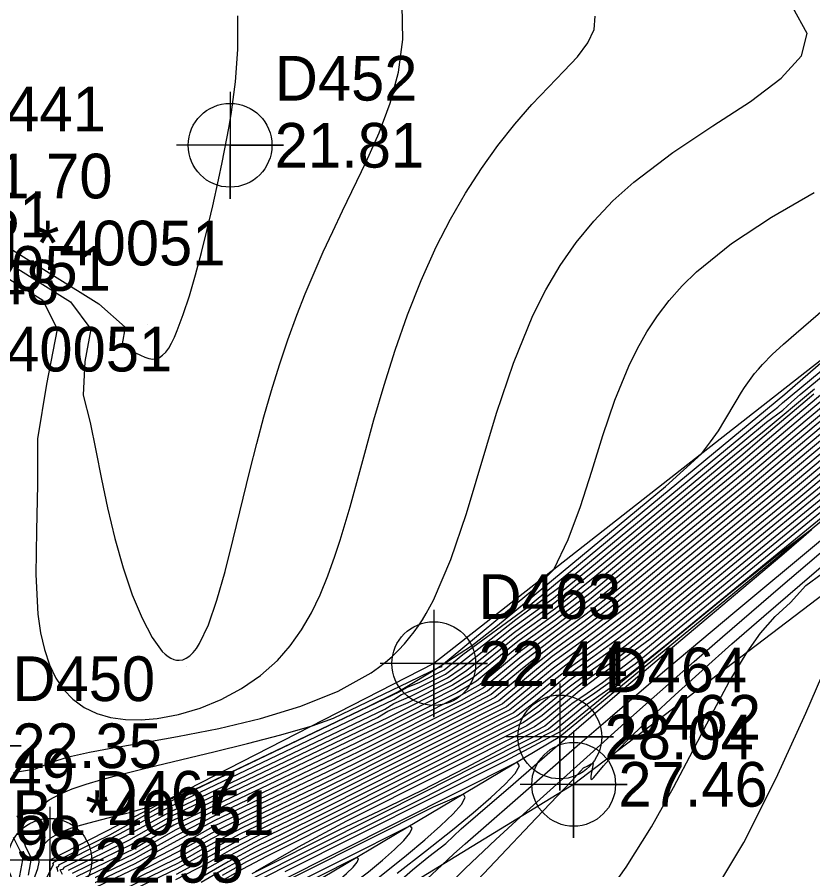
# Model space of a CAD drawing. Extents: x 2356077 to 2359823, y 225951 to 227822.
# Drawn here: x 2356632.82 to 2356677.38, y 226991.05 to 227038.77 of the extents above; entities that cross this region are included whole.
import ezdxf

# ---------------------------------------------------------------- set-up
doc = ezdxf.new("R2010")
doc.units = 0
for name, color, linetype in [('DTM Contours Major', 7, 'Continuous'), ('DTM Contours Minor', 7, 'Continuous'), ('Exist DTM Breakline', 7, 'Continuous'), ('Exist DTM Breakline Cogo Comment', 7, 'Continuous'), ('Exist DTM Breakline Cogo Elevation', 7, 'Continuous'), ('Exist DTM Breakline Cogo Number', 7, 'Continuous'), ('Exist DTM Breakline Cogo Point CELL', 7, 'Continuous'), ('Exist DTM Regular Point CELL', 7, 'Continuous'), ('Exist DTM Regular Point Cogo Elevation', 7, 'Continuous'), ('Exist DTM Regular Point Cogo Number', 7, 'Continuous'), ('PH Exist DTM Point', 7, 'Continuous')]:
    doc.layers.add(name, color=color, linetype=linetype)

msp = doc.modelspace()

# ---------------------------------------------------------------- linework, layer by layer
at = {"layer": 'DTM Contours Major'}
for points in [[(2356629.303, 227026.9), (2356635.813, 227022.844), (2356636.959, 227021.315), (2356636.611, 227019.492), (2356636.518, 227017.607), (2356636.907, 227016.089), (2356637.236, 227014.518), (2356637.546, 227012.918), (2356637.877, 227011.307), (2356638.289, 227009.599), (2356638.759, 227007.961), (2356639.273, 227006.452), (2356639.818, 227005.13), (2356640.383, 227004.052), (2356640.953, 227003.277), (2356641.114, 227003.12), (2356641.274, 227002.992), (2356641.434, 227002.894), (2356641.592, 227002.825), (2356641.749, 227002.787), (2356641.905, 227002.779), (2356642.102, 227002.813), (2356642.297, 227002.897), (2356642.488, 227003.029), (2356642.675, 227003.21), (2356642.859, 227003.439), (2356643.039, 227003.714), (2356643.54, 227004.766), (2356644.015, 227006.137), (2356644.474, 227007.756), (2356644.926, 227009.551), (2356645.849, 227013.384), (2356646.238, 227014.909), (2356646.644, 227016.408), (2356647.07, 227017.877), (2356647.517, 227019.316), (2356647.988, 227020.72), (2356648.485, 227022.088), (2356648.957, 227023.29), (2356649.45, 227024.468), (2356649.963, 227025.629), (2356650.493, 227026.781), (2356651.039, 227027.931), (2356652.365, 227030.668), (2356653.092, 227032.288), (2356653.718, 227033.96), (2356654.182, 227035.698), (2356654.422, 227037.517), (2356654.378, 227039.432)], [(2356633.859, 226989.395), (2356634.839, 226991.313), (2356634.871, 226991.324), (2356634.819, 226991.422), (2356634.869, 226991.412), (2356634.853, 226991.452), (2356634.861, 226991.473), (2356634.875, 226991.491), (2356638.015, 226993.019), (2356641.035, 226994.707), (2356654.257, 227001.028), (2356654.671, 227001.273), (2356655.363, 227001.561), (2356656.724, 227002.245), (2356657.776, 227003.109), (2356661.351, 227005.722), (2356675.811, 227017.665), (2356679.39, 227020.795)], [(2356680.26, 227019.691), (2356676.405, 227016.442), (2356673.246, 227013.767), (2356671.44, 227012.284), (2356665.065, 227007.018), (2356662.952, 227005.358), (2356660.848, 227003.837), (2356658.345, 227001.807), (2356657.32, 227001.179), (2356653.298, 226999.159), (2356652.183, 226998.621), (2356641.605, 226993.564), (2356639.419, 226992.247), (2356636.123, 226990.671)], [(2356681.648, 227017.188), (2356676.515, 227012.882), (2356674.805, 227011.467), (2356668.104, 227005.979), (2356666.778, 227004.932), (2356665.422, 227003.904), (2356664.055, 227002.904), (2356662.792, 227001.935), (2356661.625, 227000.971), (2356660.417, 227000.005), (2356650.424, 226994.985), (2356648.485, 226994.02), (2356646.654, 226993.145), (2356644.955, 226992.264), (2356643.381, 226991.381), (2356641.685, 226990.498)], [(2356677.954, 227015.918), (2356673.699, 227012.35), (2356669.7, 227009.074), (2356667.996, 227007.667), (2356666.281, 227006.272), (2356664.577, 227004.956), (2356662.849, 227003.677), (2356661.117, 227002.324), (2356659.36, 227000.872), (2356657.9, 227000.106), (2356651.822, 226997.052), (2356650.253, 226996.282), (2356645.811, 226994.158), (2356643.724, 226993.117), (2356641.848, 226992.056), (2356639.505, 226990.872)], [(2356678.591, 227012.78), (2356668.345, 227004.388), (2356666.512, 227002.96), (2356665.495, 227002.224), (2356664.478, 227001.511), (2356663.553, 227000.791), (2356662.211, 226999.683), (2356661.352, 226999.11), (2356646.791, 226991.794), (2356645.437, 226991.091), (2356644.152, 226990.361)], [(2356654.064, 226990.278), (2356654.969, 226991.051), (2356655.877, 226991.804), (2356656.824, 226992.535), (2356657.685, 226993.344), (2356658.618, 226994.144), (2356660.59, 226995.854), (2356662.791, 226997.768), (2356664.937, 226999.619), (2356666.938, 227001.329), (2356669.279, 227003.313), (2356675.635, 227008.669), (2356676.856, 227009.707), (2356677.291, 227010.099), (2356676.773, 227009.713), (2356675.381, 227008.638), (2356672.559, 227006.394), (2356663.328, 226998.833), (2356660.139, 226997.135), (2356647.814, 226990.943)], [(2356671.491, 226989.227), (2356673.506, 226992.595), (2356675.328, 226996.194), (2356676.977, 226999.821), (2356678.47, 227003.273)]]:
    msp.add_lwpolyline(points, dxfattribs=at)
at = {"layer": 'DTM Contours Minor'}
for points in [[(2356629.646, 227027.562), (2356637.397, 227022.732), (2356638.874, 227021.42), (2356638.698, 227020.497), (2356638.948, 227020.299), (2356639.208, 227020.135), (2356639.449, 227019.991), (2356639.724, 227019.845), (2356639.974, 227019.735), (2356640.203, 227019.666), (2356640.414, 227019.639), (2356640.61, 227019.657), (2356640.792, 227019.723), (2356640.973, 227019.846), (2356641.145, 227020.024), (2356641.311, 227020.254), (2356641.473, 227020.534), (2356641.633, 227020.862), (2356641.794, 227021.237), (2356642.128, 227022.134), (2356642.469, 227023.182), (2356642.81, 227024.347), (2356643.147, 227025.596), (2356643.474, 227026.894), (2356643.785, 227028.208), (2356644.108, 227029.656), (2356644.311, 227030.625), (2356644.556, 227031.876), (2356644.696, 227032.656), (2356644.827, 227033.459), (2356645.045, 227035.152), (2356645.177, 227036.953), (2356645.187, 227038.846)], [(2356632.631, 226996.502), (2356633.853, 226996.699), (2356634.691, 226997.071), (2356635.703, 226997.379), (2356636.873, 226997.645), (2356638.184, 226997.889), (2356639.617, 226998.134), (2356641.808, 226998.517), (2356644.117, 226998.972), (2356646.448, 226999.527), (2356648.709, 227000.212), (2356650.806, 227001.053), (2356652.645, 227002.08), (2356653.057, 227002.372), (2356653.448, 227002.678), (2356653.819, 227003), (2356654.171, 227003.339), (2356654.503, 227003.695), (2356654.819, 227004.07), (2356655.059, 227004.382), (2356655.289, 227004.708), (2356655.511, 227005.046), (2356655.724, 227005.398), (2356655.929, 227005.763), (2356656.128, 227006.141), (2356657.113, 227008.418), (2356657.989, 227010.995), (2356659.671, 227016.601), (2356660.608, 227019.406), (2356661.696, 227022.065), (2356662.426, 227023.51), (2356663.235, 227024.871), (2356664.127, 227026.151), (2356665.108, 227027.354), (2356666.183, 227028.483), (2356667.356, 227029.543), (2356669.53, 227031.185), (2356671.776, 227032.677), (2356673.873, 227034.053), (2356675.598, 227035.352), (2356676.729, 227036.608), (2356677.045, 227037.859), (2356676.249, 227039.301)], [(2356628.612, 227026.456), (2356634.261, 227022.936), (2356635.061, 227021.303), (2356634.475, 227018.231), (2356633.97, 227015.166), (2356633.975, 227012.599), (2356633.909, 227010.036), (2356633.878, 227007.586), (2356633.99, 227005.357), (2356634.137, 227004.32), (2356634.354, 227003.376), (2356634.641, 227002.528), (2356635.002, 227001.78), (2356635.438, 227001.135), (2356635.95, 227000.597), (2356636.579, 227000.144), (2356637.285, 226999.809), (2356638.058, 226999.586), (2356638.887, 226999.468), (2356639.761, 226999.448), (2356640.668, 226999.521), (2356641.865, 226999.742), (2356643.07, 227000.099), (2356644.255, 227000.586), (2356645.392, 227001.199), (2356646.45, 227001.93), (2356647.4, 227002.774), (2356648.12, 227003.592), (2356648.75, 227004.482), (2356649.303, 227005.437), (2356649.79, 227006.447), (2356650.224, 227007.506), (2356650.618, 227008.604), (2356650.91, 227009.505), (2356651.19, 227010.428), (2356651.462, 227011.375), (2356652.003, 227013.348), (2356652.283, 227014.377), (2356652.801, 227016.242), (2356653.368, 227018.172), (2356653.991, 227020.135), (2356654.681, 227022.102), (2356655.445, 227024.04), (2356656.293, 227025.921), (2356657.085, 227027.457), (2356657.933, 227028.919), (2356658.823, 227030.301), (2356659.746, 227031.593), (2356660.687, 227032.787), (2356661.637, 227033.876), (2356662.569, 227034.851), (2356663.441, 227035.736), (2356664.196, 227036.553), (2356664.776, 227037.326), (2356665.126, 227038.076), (2356665.189, 227038.827)], [(2356635.36, 226990.795), (2356635.227, 226991.056), (2356635.413, 226991.115), (2356635.462, 226991.205), (2356638.85, 226992.914), (2356641.387, 226994.309), (2356653.404, 227000.054), (2356653.915, 227000.369), (2356654.908, 227000.787), (2356656.91, 227001.792), (2356657.677, 227002.318), (2356660.509, 227004.552), (2356662.859, 227006.263), (2356673.56, 227015.098), (2356674.786, 227016.102), (2356675.689, 227016.782), (2356676.177, 227017.227), (2356676.662, 227017.648), (2356693.314, 227031.415)], [(2356633.455, 226990.763), (2356633.628, 226991.717), (2356633.318, 226992.331), (2356633.108, 226992.9), (2356633.149, 226993.443), (2356632.828, 226994.063), (2356633.664, 226994.284), (2356634.139, 226994.601), (2356634.626, 226994.968), (2356635.216, 226995.292), (2356635.906, 226995.584), (2356636.693, 226995.855), (2356637.574, 226996.114), (2356638.545, 226996.373), (2356640.182, 226996.783), (2356643.83, 226997.663), (2356645.722, 226998.13), (2356647.581, 226998.614), (2356649.348, 226999.112), (2356650.534, 226999.543), (2356654.776, 227001.571), (2356655.962, 227002.146), (2356656.376, 227002.354), (2356656.613, 227002.427), (2356656.589, 227002.497), (2356661.901, 227006.886), (2356662.88, 227007.865), (2356663.675, 227009.543), (2356664.361, 227011.395), (2356664.991, 227013.355), (2356665.617, 227015.36), (2356666.291, 227017.343), (2356667.065, 227019.241), (2356667.548, 227020.218), (2356668.082, 227021.153), (2356668.673, 227022.047), (2356669.328, 227022.904), (2356670.054, 227023.726), (2356670.855, 227024.515), (2356672.821, 227026.1), (2356675.052, 227027.571), (2356677.442, 227028.952)], [(2356635.106, 226990.959), (2356635.08, 226991.126), (2356635.028, 226991.23), (2356635.143, 226991.243), (2356635.159, 226991.304), (2356635.198, 226991.362), (2356638.557, 226993.063), (2356641.31, 226994.556), (2356653.922, 227000.585), (2356654.353, 227000.86), (2356655.17, 227001.191), (2356656.803, 227002.012), (2356657.545, 227002.563), (2356660.746, 227005.066), (2356663.145, 227006.85), (2356674.192, 227015.973), (2356674.933, 227016.58), (2356675.418, 227016.936), (2356675.672, 227017.189), (2356685.846, 227025.6)], [(2356630.467, 226981.533), (2356633.989, 226991.122), (2356634.055, 226991.489), (2356634.027, 226991.784), (2356633.926, 226991.978), (2356633.956, 226992.013), (2356634.121, 226992.248), (2356634.296, 226992.459), (2356634.483, 226992.648), (2356634.715, 226992.838), (2356634.97, 226993.005), (2356635.249, 226993.153), (2356635.553, 226993.285), (2356635.884, 226993.406), (2356636.245, 226993.521), (2356636.852, 226993.69), (2356638.285, 226994.054), (2356639.113, 226994.273), (2356640.017, 226994.53), (2356640.999, 226994.838), (2356643.071, 226995.692), (2356652.445, 227000.173), (2356654.133, 227001.015), (2356654.823, 227001.423), (2356656.185, 227002.247), (2356657.573, 227003.141), (2356658.263, 227003.595), (2356659.715, 227004.725), (2356669.128, 227012.502), (2356671.136, 227014.33), (2356671.651, 227015), (2356672.082, 227015.626), (2356672.449, 227016.213), (2356673.076, 227017.289), (2356673.377, 227017.788), (2356673.547, 227018.051), (2356673.725, 227018.31), (2356673.913, 227018.566), (2356674.112, 227018.821), (2356674.326, 227019.075), (2356674.554, 227019.33), (2356675.102, 227019.886), (2356675.728, 227020.467), (2356676.434, 227021.086), (2356678.075, 227022.494)], [(2356680.26, 227019.305), (2356676.441, 227016.099), (2356674.164, 227014.177), (2356673.07, 227013.265), (2356671.087, 227011.638), (2356664.96, 227006.577), (2356662.941, 227005.032), (2356660.909, 227003.57), (2356658.542, 227001.615), (2356657.443, 227000.968), (2356652.999, 226998.735), (2356651.787, 226998.148), (2356644.047, 226994.448), (2356641.678, 226993.281), (2356639.384, 226991.947), (2356636.324, 226990.484)], [(2356680.255, 227018.932), (2356676.469, 227015.76), (2356674.053, 227013.726), (2356672.889, 227012.759), (2356670.731, 227010.989), (2356666.844, 227007.778), (2356664.866, 227006.17), (2356662.923, 227004.699), (2356660.923, 227003.227), (2356658.741, 227001.425), (2356657.562, 227000.755), (2356652.701, 226998.313), (2356651.396, 226997.678), (2356643.955, 226994.121), (2356641.731, 226992.98), (2356639.386, 226991.665), (2356636.52, 226990.295)], [(2356680.24, 227018.556), (2356676.49, 227015.417), (2356673.94, 227013.274), (2356672.708, 227012.253), (2356670.38, 227010.345), (2356666.644, 227007.259), (2356664.772, 227005.769), (2356660.97, 227002.911), (2356658.944, 227001.238), (2356657.678, 227000.54), (2356652.405, 226997.891), (2356651.01, 226997.21), (2356643.864, 226993.794), (2356641.776, 226992.675), (2356639.411, 226991.393), (2356636.713, 226990.104)], [(2356635.695, 226991.033), (2356639.073, 226992.711), (2356641.446, 226994.054), (2356652.998, 226999.577), (2356653.586, 226999.942), (2356654.726, 227000.422), (2356657.055, 227001.593), (2356657.92, 227002.165), (2356660.673, 227004.362), (2356662.937, 227006.014), (2356665.244, 227007.875), (2356672.991, 227014.273), (2356674.641, 227015.625), (2356677.469, 227017.964)], [(2356680.205, 227018.166), (2356675.141, 227013.92), (2356673.819, 227012.81), (2356670.04, 227009.71), (2356666.451, 227006.744), (2356664.675, 227005.362), (2356662.877, 227004.02), (2356661.037, 227002.612), (2356659.15, 227001.054), (2356657.791, 227000.324), (2356652.113, 226997.471), (2356650.629, 226996.745), (2356646.021, 226994.542), (2356643.783, 226993.466), (2356641.815, 226992.367), (2356639.453, 226991.13), (2356636.904, 226989.912)], [(2356677.422, 227017.669), (2356674.412, 227015.121), (2356673.45, 227014.303), (2356671.76, 227012.903), (2356665.162, 227007.452), (2356662.957, 227005.688), (2356660.776, 227004.104), (2356658.144, 227001.995), (2356657.192, 227001.388), (2356653.601, 226999.584), (2356641.514, 226993.804), (2356639.27, 226992.49), (2356635.915, 226990.855)], [(2356680.077, 227016.967), (2356674.971, 227012.688), (2356673.454, 227011.434), (2356669.039, 227007.818), (2356667.491, 227006.541), (2356665.942, 227005.327), (2356664.374, 227004.14), (2356662.783, 227002.986), (2356659.789, 227000.518), (2356658.109, 226999.665), (2356651.273, 226996.23), (2356649.552, 226995.38), (2356645.426, 226993.408), (2356643.59, 226992.428), (2356641.847, 226991.425), (2356637.461, 226989.328)], [(2356680.122, 227017.369), (2356675.027, 227013.099), (2356673.576, 227011.891), (2356669.367, 227008.444), (2356667.738, 227007.099), (2356666.112, 227005.8), (2356664.477, 227004.548), (2356662.817, 227003.333), (2356661.207, 227002.044), (2356659.573, 227000.694), (2356658.007, 226999.886), (2356651.548, 226996.641), (2356649.904, 226995.832), (2356645.621, 226993.784), (2356643.661, 226992.776), (2356641.875, 226991.747), (2356639.563, 226990.616)], [(2356681.488, 227016.689), (2356676.522, 227012.517), (2356667.817, 227005.386), (2356666.536, 227004.396), (2356665.245, 227003.429), (2356663.943, 227002.489), (2356662.801, 227001.588), (2356661.738, 227000.709), (2356660.616, 226999.832), (2356650.143, 226994.57), (2356648.139, 226993.572), (2356646.399, 226992.738), (2356644.797, 226991.884), (2356643.304, 226991.033)], [(2356679.982, 227016.159), (2356676.51, 227013.246), (2356674.858, 227011.869), (2356668.406, 227006.584), (2356667.017, 227005.469), (2356665.597, 227004.379), (2356664.164, 227003.317), (2356662.784, 227002.283), (2356661.514, 227001.234), (2356660.214, 227000.176), (2356650.707, 226995.4), (2356648.836, 226994.472), (2356646.922, 226993.556), (2356645.11, 226992.645), (2356643.452, 226991.73), (2356641.722, 226990.799)], [(2356678.125, 227014.969), (2356674.917, 227012.277), (2356668.718, 227007.198), (2356667.255, 227006.005), (2356665.77, 227004.853), (2356664.27, 227003.729), (2356662.779, 227002.634), (2356660.006, 227000.345), (2356650.989, 226995.814), (2356649.192, 226994.925), (2356647.197, 226993.971), (2356645.263, 226993.027), (2356643.522, 226992.079), (2356641.772, 226991.106), (2356637.652, 226989.136)], [(2356678.342, 227013.679), (2356676.543, 227012.176), (2356669.183, 227006.147), (2356667.515, 227004.791), (2356666.289, 227003.858), (2356665.064, 227002.953), (2356663.828, 227002.074), (2356662.812, 227001.242), (2356661.853, 227000.45), (2356660.809, 226999.656), (2356649.859, 226994.155), (2356647.795, 226993.124), (2356646.16, 226992.328), (2356644.635, 226991.504), (2356643.224, 226990.685)], [(2356678.401, 227013.357), (2356676.583, 227011.851), (2356668.908, 227005.565), (2356667.196, 227004.187), (2356666.036, 227003.317), (2356663.736, 227001.652), (2356661.97, 227000.193), (2356660.996, 226999.477), (2356649.573, 226993.738), (2356647.454, 226992.678), (2356645.918, 226991.917), (2356644.472, 226991.124), (2356643.131, 226990.339)], [(2356679.678, 227013.312), (2356668.259, 227003.96), (2356666.228, 227002.475), (2356665.311, 227001.839), (2356664.29, 227001.045), (2356662.422, 226999.502), (2356661.798, 226999.061), (2356651.27, 226993.771), (2356648.559, 226992.328), (2356646.151, 226990.938)], [(2356655.253, 226990.065), (2356656.6, 226991.326), (2356657.277, 226991.944), (2356657.911, 226992.512), (2356659.082, 226993.538), (2356660.708, 226994.948), (2356664.335, 226998.125), (2356666.02, 226999.587), (2356668.036, 227001.313), (2356669.193, 227002.294), (2356673.001, 227005.49), (2356682.483, 227013.387)], [(2356678.466, 227013.039), (2356672.629, 227008.254), (2356668.629, 227004.978), (2356666.864, 227003.578), (2356665.773, 227002.774), (2356664.683, 227001.995), (2356663.647, 227001.223), (2356662.09, 226999.937), (2356661.177, 226999.295), (2356647.115, 226992.233), (2356645.674, 226991.505), (2356644.306, 226990.743)], [(2356679.229, 227012.229), (2356667.425, 227002.561), (2356665.162, 227000.935), (2356664.43, 227000.441), (2356663.687, 226999.838), (2356662.573, 226998.918), (2356661.751, 226998.491), (2356658.443, 226996.83), (2356655.578, 226995.375), (2356653.017, 226994.103), (2356645.776, 226990.465)], [(2356679.594, 227012.17), (2356669.406, 227003.826), (2356667.036, 227001.925), (2356664.436, 227000.099), (2356662.915, 226998.846), (2356662.35, 226998.576), (2356662.047, 226998.367), (2356658.528, 226996.599), (2356655.592, 226995.094), (2356652.886, 226993.743), (2356650.324, 226992.477), (2356647.897, 226991.258), (2356645.778, 226990.175)], [(2356678.971, 227012.376), (2356667.614, 227003.074), (2356665.601, 227001.527), (2356664.746, 227000.926), (2356663.888, 227000.34), (2356663.23, 226999.815), (2356662.369, 226999.104), (2356660.931, 226998.352), (2356657.945, 226996.763), (2356655.487, 226995.488), (2356653.058, 226994.32), (2356650.916, 226993.321), (2356645.971, 226990.836)], [(2356654.997, 226986.671), (2356661.888, 226993.947), (2356663.865, 226996.013), (2356664.538, 226996.767), (2356664.745, 226996.862), (2356664.953, 226996.987), (2356665.07, 226997.005), (2356664.952, 226996.306), (2356664.943, 226996.201), (2356664.95, 226996.136), (2356664.976, 226996.112), (2356665.023, 226996.134), (2356665.113, 226996.222), (2356665.661, 226996.879), (2356665.956, 226997.219), (2356666.317, 226997.616), (2356667.205, 226998.526), (2356668.331, 226999.612), (2356669.665, 227000.85), (2356671.178, 227002.218), (2356672.842, 227003.693), (2356674.627, 227005.252), (2356677.311, 227007.563), (2356680.135, 227009.965)], [(2356655.764, 226989.013), (2356657.905, 226991.132), (2356659.618, 226992.757), (2356660.985, 226994.008), (2356664.902, 226997.528), (2356666.844, 226999.275), (2356668.001, 227000.308), (2356669.292, 227001.453), (2356670.726, 227002.712), (2356672.309, 227004.091), (2356675.568, 227006.894), (2356679.216, 227009.997)], [(2356665.55, 226989.291), (2356666.915, 226991.208), (2356668.342, 226993.468), (2356669.579, 226995.661), (2356670.679, 226997.759), (2356671.696, 226999.737), (2356672.682, 227001.569), (2356673.691, 227003.227), (2356674.45, 227004.292), (2356675.259, 227005.227), (2356676.114, 227006.012), (2356676.984, 227006.958), (2356677.888, 227007.645)], [(2356654.101, 226990.871), (2356655.693, 226992.104), (2356657.197, 226993.294), (2356658.35, 226994.238), (2356659.354, 226995.101), (2356660.156, 226995.85), (2356660.703, 226996.451), (2356660.941, 226996.87), (2356660.818, 226997.073), (2356644.084, 226988.665)], [(2356652.93, 226990.521), (2356654.628, 226991.884), (2356655.655, 226992.743), (2356656.534, 226993.518), (2356657.228, 226994.186), (2356657.699, 226994.72), (2356657.91, 226995.098), (2356657.824, 226995.295), (2356656.111, 226994.565), (2356645.16, 226989.064)], [(2356643.246, 226987.698), (2356640.909, 226986.581), (2356640.694, 226986.342), (2356640.776, 226985.802), (2356641.9, 226983.589), (2356642.652, 226983.708), (2356646.121, 226986.382), (2356648.146, 226987.879), (2356649.663, 226988.867), (2356651.142, 226989.912), (2356652.505, 226990.953), (2356653.288, 226991.596), (2356653.956, 226992.186), (2356654.477, 226992.699), (2356654.818, 226993.109), (2356654.946, 226993.39), (2356654.829, 226993.517), (2356643.246, 226987.698)], [(2356632.925, 226990.424), (2356633.141, 226991.615), (2356633.135, 226991.864), (2356632.615, 226992.866)], [(2356642.827, 226987.214), (2356641.01, 226986.346), (2356641.091, 226986.249), (2356640.914, 226985.75), (2356641.789, 226984.026), (2356642.661, 226984.414), (2356645.458, 226986.571), (2356647.12, 226987.832), (2356648.215, 226988.535), (2356649.276, 226989.272), (2356650.247, 226990.002), (2356650.801, 226990.45), (2356651.27, 226990.858), (2356651.63, 226991.21), (2356651.86, 226991.486), (2356651.936, 226991.668), (2356651.834, 226991.74), (2356642.827, 226987.214)]]:
    msp.add_lwpolyline(points, dxfattribs=at)
at = {"layer": 'Exist DTM Breakline'}
for points in [[(2356732.647, 227097.121), (2356743.457, 227064.303), (2356707.447, 227028.908), (2356663.982, 226995.84), (2356642.282, 226982.572)], [(2356730.086, 227095.133), (2356740.594, 227064.572), (2356703.676, 227031.845), (2356663.207, 226998.49), (2356641.363, 226985.524)], [(2356734.478, 227064.277), (2356698.288, 227035.595), (2356656.152, 227002.595), (2356634.655, 226991.589)]]:
    msp.add_lwpolyline(points, dxfattribs=at)
at = {"layer": 'Exist DTM Breakline Cogo Point CELL'}
for points in [[(2356656.152, 227005.595), (2356656.152, 226999.595), (2356656.152, 227002.595), (2356659.152, 227002.595), (2356653.152, 227002.595)], [(2356663.207, 227001.49), (2356663.207, 226995.49), (2356663.207, 226998.49), (2356666.207, 226998.49), (2356660.207, 226998.49)], [(2356630.061, 227000.999), (2356630.061, 226994.999), (2356630.061, 226997.999), (2356633.061, 226997.999), (2356627.061, 226997.999)], [(2356663.982, 226998.84), (2356663.982, 226992.84), (2356663.982, 226995.84), (2356666.982, 226995.84), (2356660.982, 226995.84)], [(2356634.655, 226994.589), (2356634.655, 226988.589), (2356634.655, 226991.589), (2356637.655, 226991.589), (2356631.655, 226991.589)]]:
    msp.add_lwpolyline(points, dxfattribs=at)
for centre in [(2356656.152, 227002.595), (2356663.207, 226998.49), (2356663.982, 226995.84), (2356634.655, 226991.589)]:
    msp.add_circle(centre, 2.344, dxfattribs=at)
at = {"layer": 'Exist DTM Regular Point CELL'}
msp.add_lwpolyline([(2356644.747, 227034.597), (2356644.747, 227028.597), (2356644.747, 227031.597), (2356647.747, 227031.597), (2356641.747, 227031.597)], dxfattribs=at)
msp.add_circle((2356644.747, 227031.597), 2.344, dxfattribs=at)
at = {"layer": 'PH Exist DTM Point'}
for p, q in [((2356640.139, 227021.592), (2356640.139, 227021.592)), ((2356642.289, 227002.431), (2356642.289, 227002.431))]:
    msp.add_line(p, q, dxfattribs=at)

# ---------------------------------------------------------------- texts
at = {"layer": 'Exist DTM Breakline Cogo Comment'}
for s, p in [('BL*40051', (2356629.801, 227024.877)), ('EL*40051', (2356623.385, 227023.456)), ('EL*40051', (2356626.82, 227018.94)), ('BL*40051', (2356632.561, 226992.999))]:
    msp.add_text(s, height=2.5, dxfattribs=at).set_placement(p)
at = {"layer": 'Exist DTM Breakline Cogo Elevation'}
for s, p in [('21.70', (2356629.801, 227028.627)), ('23.48', (2356626.82, 227022.69)), ('22.44', (2356658.652, 227001.345)), ('28.04', (2356665.707, 226997.24)), ('22.35', (2356632.561, 226996.749)), ('27.46', (2356666.482, 226994.59)), ('18.98', (2356628.067, 226991.575)), ('22.95', (2356637.155, 226990.339))]:
    msp.add_text(s, height=2.5, dxfattribs=at).set_placement(p)
at = {"layer": 'Exist DTM Breakline Cogo Number'}
for s, p in [('D441', (2356629.801, 227032.377)), ('D451', (2356626.82, 227026.44)), ('D463', (2356658.652, 227005.095)), ('D464', (2356665.707, 227000.99)), ('D450', (2356632.561, 227000.499)), ('D462', (2356666.482, 226998.34)), ('D449', (2356628.067, 226995.325)), ('D467', (2356637.155, 226994.089))]:
    msp.add_text(s, height=2.5, dxfattribs=at).set_placement(p)
at = {"layer": 'Exist DTM Regular Point Cogo Elevation'}
msp.add_text('21.81', height=2.5, dxfattribs=at).set_placement((2356647.247, 227030.347))
at = {"layer": 'Exist DTM Regular Point Cogo Number'}
msp.add_text('D452', height=2.5, dxfattribs=at).set_placement((2356647.247, 227034.097))

doc.saveas('drawing.dxf')
